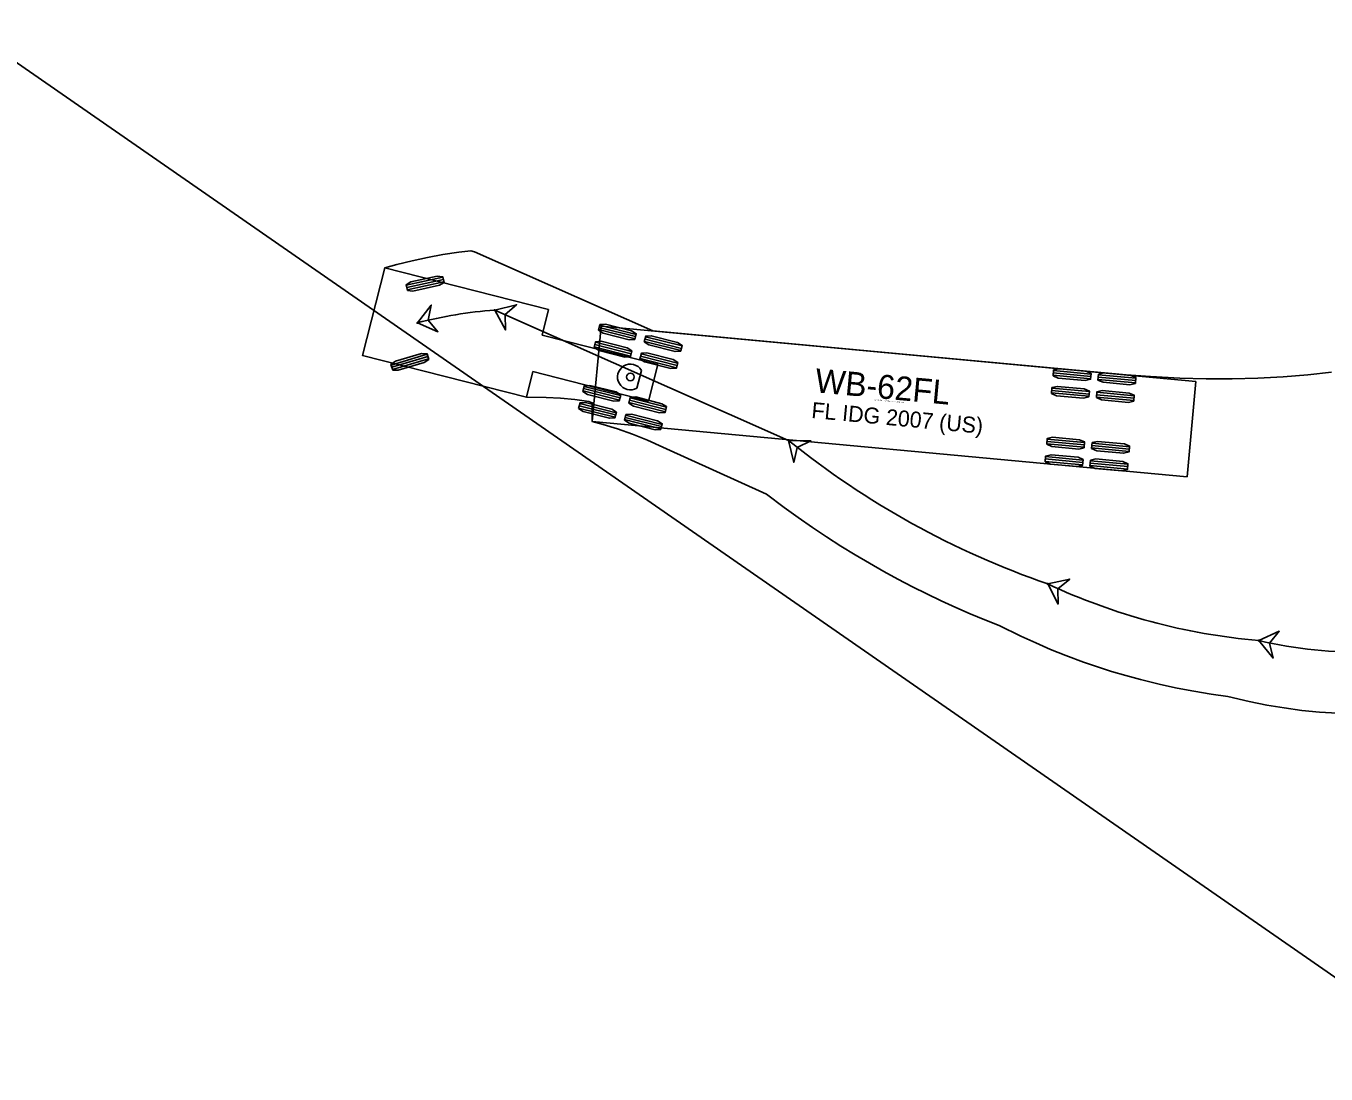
# Model space of a CAD drawing. Extents: x 2096670 to 2098561, y 684033 to 689893.
# Drawn here: x 2097524.8 to 2097640.1, y 686140.7 to 686233.6 of the extents above; entities that cross this region are included whole.
import ezdxf

# ---------------------------------------------------------------- set-up
doc = ezdxf.new("R2010")
doc.units = 0
doc.layers.add('Default', color=7, linetype='Continuous')
doc.layers.add('Old_Level_63', color=7, linetype='Continuous')

msp = doc.modelspace()

# ---------------------------------------------------------------- linework, layer by layer
at = {"layer": 'Default'}
msp.add_line((2097519.27, 686233.6), (2097653.25, 686140.68), dxfattribs=at)
at = {"layer": 'Old_Level_63'}
for p, q in [((2097556.61, 686212.15), (2097554.63, 686204.39)), ((2097571.14, 686208.45), (2097556.61, 686212.15)), ((2097558.52, 686210.61), (2097561.77, 686211.32)), ((2097558.56, 686210.41), (2097561.82, 686211.11)), ((2097558.6, 686210.2), (2097561.86, 686210.91)), ((2097592.42, 686196.85), (2097566.37, 686208.41)), ((2097570.57, 686206.19), (2097571.14, 686208.45)), ((2097575.8, 686206.99), (2097575.02, 686198.52)), ((2097575.58, 686206.68), (2097578.81, 686205.86)), ((2097575.63, 686206.88), (2097578.86, 686206.06)), ((2097575.68, 686207.08), (2097578.91, 686206.26)), ((2097628.57, 686202.09), (2097575.8, 686206.99)), ((2097580.84, 686203.58), (2097570.57, 686206.19)), ((2097575.29, 686205.56), (2097578.52, 686204.74)), ((2097579.65, 686205.64), (2097582.88, 686204.82)), ((2097579.7, 686205.84), (2097582.93, 686205.02)), ((2097579.75, 686206.05), (2097582.98, 686205.23)), ((2097554.63, 686204.39), (2097569.17, 686200.7)), ((2097554.63, 686204.39), (2097554.63, 686204.39)), ((2097557.18, 686203.54), (2097560.37, 686204.49)), ((2097557.24, 686203.34), (2097560.43, 686204.29)), ((2097575.19, 686205.16), (2097578.42, 686204.34)), ((2097575.24, 686205.36), (2097578.47, 686204.54)), ((2097579.31, 686204.33), (2097582.54, 686203.5)), ((2097579.36, 686204.53), (2097582.59, 686203.71)), ((2097557.3, 686203.14), (2097560.49, 686204.09)), ((2097579.26, 686204.12), (2097582.49, 686203.3)), ((2097580.02, 686200.35), (2097580.84, 686203.58)), ((2097569.17, 686200.7), (2097569.75, 686202.96)), ((2097569.75, 686202.96), (2097580.02, 686200.35)), ((2097578.98, 686201.5), (2097579.38, 686203.06)), ((2097615.9, 686202.63), (2097619.22, 686202.33)), ((2097615.92, 686202.84), (2097619.24, 686202.53)), ((2097615.94, 686203.05), (2097619.26, 686202.74)), ((2097619.89, 686202.26), (2097623.21, 686201.96)), ((2097619.91, 686202.47), (2097623.23, 686202.16)), ((2097619.93, 686202.68), (2097623.24, 686202.37)), ((2097627.79, 686193.62), (2097628.57, 686202.09)), ((2097574.2, 686201.25), (2097577.43, 686200.43)), ((2097574.25, 686201.45), (2097577.48, 686200.63)), ((2097574.3, 686201.65), (2097577.53, 686200.83)), ((2097615.76, 686201.07), (2097619.08, 686200.77)), ((2097615.78, 686201.28), (2097619.1, 686200.97)), ((2097615.8, 686201.49), (2097619.12, 686201.18)), ((2097619.76, 686200.91), (2097623.08, 686200.6)), ((2097619.78, 686201.12), (2097623.1, 686200.81)), ((2097573.81, 686199.73), (2097577.04, 686198.91)), ((2097573.86, 686199.93), (2097577.09, 686199.11)), ((2097573.91, 686200.14), (2097577.14, 686199.31)), ((2097578.27, 686200.22), (2097581.5, 686199.39)), ((2097578.32, 686200.42), (2097581.55, 686199.6)), ((2097578.37, 686200.62), (2097581.6, 686199.8)), ((2097619.74, 686200.7), (2097623.06, 686200.4)), ((2097575.02, 686198.52), (2097627.79, 686193.62)), ((2097575.02, 686198.52), (2097575.02, 686198.52)), ((2097577.88, 686198.7), (2097581.11, 686197.88)), ((2097577.93, 686198.9), (2097581.16, 686198.08)), ((2097577.98, 686199.1), (2097581.21, 686198.28)), ((2097615.34, 686196.56), (2097618.66, 686196.25)), ((2097615.36, 686196.77), (2097618.68, 686196.46)), ((2097615.38, 686196.98), (2097618.7, 686196.67)), ((2097619.34, 686196.4), (2097622.66, 686196.09)), ((2097619.36, 686196.61), (2097622.68, 686196.3)), ((2097615.21, 686195.21), (2097618.53, 686194.9)), ((2097615.23, 686195.42), (2097618.55, 686195.11)), ((2097619.32, 686196.19), (2097622.64, 686195.88)), ((2097615.2, 686195), (2097618.51, 686194.69)), ((2097619.18, 686194.63), (2097622.5, 686194.32)), ((2097619.2, 686194.84), (2097622.52, 686194.53)), ((2097619.22, 686195.05), (2097622.54, 686194.74))]:
    msp.add_line(p, q, dxfattribs=at)
for points in [[(2097641.12, 686172.67), (2097639.54, 686172.77), (2097637.97, 686172.92), (2097636.41, 686173.13), (2097634.85, 686173.39), (2097633.3, 686173.7), (2097631.4, 686174.16), (2097629.91, 686174.37), (2097628.4, 686174.62), (2097626.9, 686174.9), (2097625.42, 686175.22), (2097623.64, 686175.65), (2097622.35, 686176.01), (2097621.08, 686176.38), (2097619.83, 686176.78), (2097618.6, 686177.2), (2097617.03, 686177.79), (2097615.68, 686178.33), (2097614.36, 686178.9), (2097613.05, 686179.49), (2097611.13, 686180.45), (2097609.84, 686180.96), (2097608.55, 686181.49), (2097607.26, 686182.05), (2097605.98, 686182.64), (2097604.7, 686183.25), (2097603.42, 686183.88), (2097602.14, 686184.55), (2097600.87, 686185.24), (2097599.6, 686185.96), (2097598.33, 686186.71), (2097597.07, 686187.49), (2097595.81, 686188.3), (2097594.55, 686189.14), (2097593.29, 686190.01), (2097592.04, 686190.92), (2097590.47, 686192.08), (2097581.28, 686196.27), (2097579.93, 686196.87), (2097578.59, 686197.4), (2097577.25, 686197.87), (2097575.98, 686198.26), (2097575.02, 686198.52), (2097575.02, 686200.19), (2097574.72, 686200.3), (2097573.46, 686200.48), (2097572.19, 686200.6), (2097570.93, 686200.67), (2097569.17, 686200.7), (2097554.63, 686204.39), (2097556.61, 686212.15), (2097557.68, 686212.44), (2097559.04, 686212.78), (2097560.39, 686213.07), (2097561.77, 686213.33), (2097563.18, 686213.55), (2097564.23, 686213.68), (2097564.58, 686213.58), (2097580.38, 686206.57), (2097601.33, 686204.62), (2097622.38, 686202.68), (2097624.55, 686202.52), (2097627.13, 686202.39), (2097629.47, 686202.32), (2097631.8, 686202.32), (2097634.07, 686202.37), (2097636.3, 686202.49), (2097638.49, 686202.67), (2097640.61, 686202.92)], [(2097559.5, 686207.28), (2097561.33, 686206.49), (2097560.47, 686207.53), (2097560.74, 686208.85), (2097559.5, 686207.28)], [(2097566.37, 686208.41), (2097567.32, 686206.66), (2097567.28, 686208.01), (2097568.31, 686208.88), (2097566.37, 686208.41)], [(2097592.42, 686196.85), (2097592.89, 686194.91), (2097593.2, 686196.23), (2097594.42, 686196.81), (2097592.42, 686196.85)], [(2097615.42, 686184.13), (2097616.34, 686182.35), (2097616.33, 686183.7), (2097617.38, 686184.56), (2097615.42, 686184.13)], [(2097634.14, 686179.1), (2097635.41, 686177.56), (2097635.11, 686178.88), (2097635.96, 686179.93), (2097634.14, 686179.1)]]:
    msp.add_lwpolyline(points, dxfattribs=at)
for points in [[(2097558.62, 686210.15), (2097558.51, 686210.66), (2097558.93, 686210.91), (2097561.27, 686211.42), (2097561.76, 686211.37), (2097561.87, 686210.86), (2097561.45, 686210.61), (2097559.1, 686210.1)], [(2097559.5, 686207.28), (2097561.33, 686206.49), (2097560.47, 686207.53), (2097560.74, 686208.85)], [(2097566.37, 686208.41), (2097567.32, 686206.66), (2097567.28, 686208.01), (2097568.31, 686208.88)], [(2097575.56, 686206.63), (2097575.69, 686207.13), (2097576.18, 686207.17), (2097578.51, 686206.58), (2097578.92, 686206.31), (2097578.79, 686205.81), (2097578.3, 686205.77), (2097575.98, 686206.36)], [(2097575.18, 686205.11), (2097575.31, 686205.61), (2097575.8, 686205.65), (2097578.12, 686205.06), (2097578.54, 686204.79), (2097578.41, 686204.29), (2097577.92, 686204.25), (2097575.59, 686204.84)], [(2097579.63, 686205.59), (2097579.76, 686206.1), (2097580.25, 686206.13), (2097582.58, 686205.54), (2097582.99, 686205.28), (2097582.87, 686204.77), (2097582.37, 686204.73), (2097580.05, 686205.33)], [(2097557.31, 686203.09), (2097557.16, 686203.59), (2097557.57, 686203.88), (2097559.87, 686204.56), (2097560.36, 686204.54), (2097560.51, 686204.04), (2097560.1, 686203.76), (2097557.8, 686203.08)], [(2097579.25, 686204.07), (2097579.38, 686204.58), (2097579.87, 686204.62), (2097582.19, 686204.02), (2097582.61, 686203.76), (2097582.48, 686203.25), (2097581.99, 686203.22), (2097579.66, 686203.81)], [(2097615.9, 686202.58), (2097615.95, 686203.1), (2097616.43, 686203.21), (2097618.82, 686202.99), (2097619.27, 686202.79), (2097619.22, 686202.28), (2097618.74, 686202.16), (2097616.35, 686202.38)], [(2097619.88, 686202.21), (2097619.93, 686202.73), (2097620.41, 686202.84), (2097622.8, 686202.62), (2097623.25, 686202.42), (2097623.2, 686201.91), (2097622.72, 686201.79), (2097620.33, 686202.01)], [(2097574.18, 686201.2), (2097574.31, 686201.7), (2097574.8, 686201.74), (2097577.13, 686201.15), (2097577.54, 686200.88), (2097577.41, 686200.38), (2097576.92, 686200.34), (2097574.6, 686200.93)], [(2097615.75, 686201.02), (2097615.8, 686201.54), (2097616.28, 686201.65), (2097618.67, 686201.43), (2097619.12, 686201.23), (2097619.07, 686200.72), (2097618.59, 686200.6), (2097616.2, 686200.82)], [(2097619.74, 686200.65), (2097619.79, 686201.17), (2097620.26, 686201.28), (2097622.65, 686201.06), (2097623.1, 686200.86), (2097623.06, 686200.35), (2097622.58, 686200.23), (2097620.19, 686200.45)], [(2097573.8, 686199.68), (2097573.93, 686200.19), (2097574.42, 686200.22), (2097576.74, 686199.63), (2097577.16, 686199.36), (2097577.03, 686198.86), (2097576.54, 686198.82), (2097574.21, 686199.42)], [(2097578.25, 686200.17), (2097578.38, 686200.67), (2097578.87, 686200.71), (2097581.2, 686200.11), (2097581.61, 686199.85), (2097581.49, 686199.34), (2097580.99, 686199.31), (2097578.67, 686199.9)], [(2097577.87, 686198.65), (2097578, 686199.15), (2097578.49, 686199.19), (2097580.81, 686198.6), (2097581.23, 686198.33), (2097581.1, 686197.83), (2097580.61, 686197.79), (2097578.28, 686198.38)], [(2097592.42, 686196.85), (2097592.89, 686194.91), (2097593.2, 686196.23), (2097594.42, 686196.81)], [(2097615.34, 686196.51), (2097615.38, 686197.03), (2097615.86, 686197.14), (2097618.25, 686196.92), (2097618.7, 686196.72), (2097618.65, 686196.2), (2097618.18, 686196.09), (2097615.79, 686196.31)], [(2097619.32, 686196.14), (2097619.37, 686196.66), (2097619.85, 686196.77), (2097622.24, 686196.55), (2097622.69, 686196.35), (2097622.64, 686195.83), (2097622.16, 686195.72), (2097619.77, 686195.94)], [(2097615.19, 686194.95), (2097615.24, 686195.47), (2097615.72, 686195.58), (2097618.11, 686195.36), (2097618.56, 686195.16), (2097618.51, 686194.64), (2097618.03, 686194.53), (2097615.64, 686194.75)], [(2097619.17, 686194.58), (2097619.22, 686195.1), (2097619.7, 686195.21), (2097622.09, 686194.99), (2097622.54, 686194.79), (2097622.49, 686194.27), (2097622.01, 686194.16), (2097619.62, 686194.38)], [(2097615.42, 686184.13), (2097616.34, 686182.35), (2097616.33, 686183.7), (2097617.38, 686184.56)], [(2097634.14, 686179.1), (2097635.41, 686177.56), (2097635.11, 686178.88), (2097635.96, 686179.93)]]:
    msp.add_lwpolyline(points, close=True, dxfattribs=at)
for centre, radius in [((2097566.37, 686208.41), 0.0417), ((2097566.37, 686208.41), 0.0417), ((2097559.5, 686207.28), 0.0417), ((2097578.4, 686202.48), 0.34), ((2097592.42, 686196.85), 0.0417), ((2097592.42, 686196.85), 0.0417), ((2097615.42, 686184.13), 0.0417), ((2097615.42, 686184.13), 0.0417), ((2097634.14, 686179.1), 0.0417), ((2097634.14, 686179.1), 0.0417)]:
    msp.add_circle(centre, radius, dxfattribs=at)
for centre, radius, start, end in [((2097569.55, 686167.54), 41, 94.455, 104.1957), ((2097578.4, 686202.48), 1.14, 30.7335, 300.7335), ((2097640.56, 686256.71), 76.81, 231.1938, 250.9003), ((2097638.93, 686234.31), 55.41, 244.8979, 265.0383), ((2097643.29, 686219.07), 41, 257.1037, 285.1345)]:
    msp.add_arc(centre, radius, start, end, dxfattribs=at)

# ---------------------------------------------------------------- texts
for s, height, p in [('WB-62FL', 2.125, (2097594.71, 686201.13)), ('FL IDG 2007 (US)', 1.4167, (2097594.42, 686198.85)), ('(c) 2023 Transoft Solutions, Inc. All rights reserved.', 0.085, (2097600.06, 686200.42))]:
    msp.add_text(s, height=height, rotation=354.6927, dxfattribs=at).set_placement(p)

doc.saveas('drawing.dxf')
